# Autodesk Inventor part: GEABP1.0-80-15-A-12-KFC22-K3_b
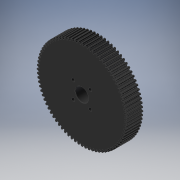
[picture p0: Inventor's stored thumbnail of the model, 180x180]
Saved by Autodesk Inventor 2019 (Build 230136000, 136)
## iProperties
Created: 2022-11
Part Number: GEABP1.0-80-15-A-12-KFC22-K3_b
Material: Generic
Catalog Web Link: www.cadenas.de
Description: GEABM, GEABMS, GEABMT, GEABP, GEABPS, GEABPT, GEABA, GEABAS, GEABAT_body-Plastic Spur Gears - Pressure Angle 20 Degrees, Module 0.5/0.8/1.0/1.5/2.0/2.5/3.0
Vendor: MISUMI
Document SubType Name: Modeling
Designer: psAdmin
Manufacturer: MISUMI
Mass: 72.9245 g
Surface Area: 182.111 cm^2
Volume: 72.9245 cm^3
Density: 1 g/cm^3
Appearance: PSOLRGB-175-175-175
Category: PARTsolutions
Company: MISUMI
Title: GEABP1.0-80-15-A-12-KFC22-K3
Author: Cadenas PARTsolutions
Comments: Plastic Spur Gears - Pressure Angle 20 Degrees, Module 0.5/0.8/1.0/1.5/2.0/2.5/3.0
PSOL_IDENT_0: {$CADENAS_DATA/23d-libs/misumi/metric/54_spur_gears/geabms20/geabms20.prj},408 {VTYP=3D},{NB=GEABP1.
PSOL_IDENT_1: 0-80-15-A-12-KFC22-K3_b},{LINA=GEABP1.0-80-15-A-12-KFC22-K3},{NN=GEABM, GEABMS, GEABMT, GEABP, GEABP
PSOL_IDENT_2: S, GEABPT, GEABA, GEABAS, GEABAT_body},{DATE=17.10.2022 23:48:33},{GEOMDATE=14.09.2022 05:11:00},{VE
PSOL_IDENT_3: RSION=},{LINEID=30},{WBVAR=MATSG,MATCR,NT,B,TS,PS,ALT1,ALT2,TPC,ALT11,ALT10,BS,ALT3,Z,J,ALT4,Q,R,S,T
PSOL_IDENT_4: ,ALT5,LFC,LTC,MALT5,ALT6,KFC,KTC,K},{WBNUMERIC=NT,B,BS,Z,J,Q,R,S,T,LFC,LTC,KFC,KTC,K}  {NB=GEABP1.0-
PSOL_IDENT_5: 80-15-A-12-KFC22-K3_b},{LINA=GEABP1.0-80-15-A-12-KFC22-K3},{KT=DUMMY},{PN=GEABP1.0-80-15-A-12-KFC22-
PSOL_IDENT_6: K3},{TYPE=GEABP},{MATSG=PW},{MATSGALG='MCN','MC Nylon','PW','Polyacetal White','PB','Polyacetal Blue'
PSOL_IDENT_7: },{MATCR=},{MATCRALG='','-','S45C','1045 Carbon Steel','SUS304','304 Stainless Steel'},{MOD=1.0},{MO
PSOL_IDENT_8: D1=1.0},{NT=80},{NTALG=15,16,18,20,22,24,25,26,28,30,32,35,36,40,45,48,50,55,60,70,75,80,90,100,120}
PSOL_IDENT_9: ,{B=15},{BALG=10,15},{TS=A},{TSALG='A','A','B','B'},{TSPN=-A},{PS=12},{PSALG='10','10','11','11','12'
PSOL_IDENT_10: ,'12','13','13','14','14','15','15','16','16','17','17','18','18','19','19','20','20','21','21','22'
PSOL_IDENT_11: ,'22','23','23','24','24','25','25','26','26','27','27','28','28'},{PSCRL='10','10','11','11','12','
PSOL_IDENT_12: 12','13','13','14','14','15','15','16','16','17','17','18','18','19','19','20','20','21','21','22','
PSOL_IDENT_13: 22','23','23','24','24','25','25','26','26','27','27','28','28'},{PSCRW='10','10','12','12','15','15'
PSOL_IDENT_14: ,'20','20'},{DD=80.0},{DD05=40},{DD08=64},{DD10=80},{DD15=120},{DD20=0},{DD25=0},{DD30=0},{D=82.0},{
PSOL_IDENT_15: D05=41},{D08=65.6},{D10=82},{D15=123},{D20=0},{D25=0},{D30=0},{G=77.50},{G05=38.75},{G08=62},{G10=77
PSOL_IDENT_16: .5},{G15=116.25},{G20=0},{G25=0},{G30=0},{H=0.0},{L=0},{LL1=0},{LL2=0.0},{M=-},{M3D=0},{P=12.00},{DD
PSOL_IDENT_17: 1=0},{CIFR=15},{CIFM=0},{CIFK=0},{CIFTAP=0},{ALT1=},{ALT1ALG='','Not applicable'},{ALT1PN=},{ALT2=},
PSOL_IDENT_18: {ALT2ALG='','Not applicable'},{TPC=N/A},{TPCALG='N/A'},{ALT2PN=},{KC=0},{ALT11=},{ALT11ALG='','Not a
PSOL_IDENT_19: pplicable'},{ALT11PN=},{DEG=0},{ALT10=},{ALT10ALG= '','Not applicable' },{ALT10PN=},{BS=0.0},{BSALG=
PSOL_IDENT_20: 0},{BSMIN=3},{BSMINALG=3.000},{BSMAX=0},{LL13D=0},{LL23D=0},{LBS=15},{ALT3=},{ALT3ALG= '','w/o Stepp
PSOL_IDENT_21: ed Hole','DHL','with DHL (Stepped Hole)','DHR','with DHR (Stepped Hole)' },{ALT3PN=},{ZJPN=},{ALT31=
PSOL_IDENT_22: 1},{ALT32=1},{Z=0},{ZALG=0},{ZMINL=14},{ZMAXL=73},{ZMINR=14},{ZMAXR=73},{ZPN=},{J=0.0},{JALG=0},{JMI
PSOL_IDENT_23: N=2},{JMAX=0},{JPN=},{ALT4=},{ALT4ALG= '','w/o WDH (Both Ends Stepped Hole)','WDH','with WDH (Both E
PSOL_IDENT_24: nds Stepped Hole)' },{ALT4PN=},{QRSTPN=},{LB=15.000},{Q=0},{QALG=0},{QMIN=14},{QMAX=73},{QPN=},{R=0}
PSOL_IDENT_25: ,{RALG=0},{RMIN=14},{RMAX=73},{RPN=},{S=0},{SALG=0},{SMIN=3},{SMAX=9},{SPN=},{T=0},{TALG=0},{TMIN=3}
PSOL_IDENT_26: ,{TMAX=0},{TPN=},{ALT5=},{ALT5ALG= '','w/o Side Slotted Hole','LFC','with LFC (Side Slotted Hole)','
PSOL_IDENT_27: LTC','with LTC (Side Slotted Hole)' },{LFC=0},{LFCALG=0},{LTC=0},{LTCALG=0},{LPCDMIN=20},{LPCDMAX=70
PSOL_IDENT_28: },{LCMAX=73},{MALT5=N/A},{MALT5ALG= 'N/A' },{LCMAX2=70},{C=0.0},{ALT5PN=},{ALT6=KFC},{ALT6ALG= '','w
PSOL_IDENT_29: /o Side Through Hole','KFC','with KFC (Side Through Hole)','KTC','with KTC (Side Through Hole)' },{A
PSOL_IDENT_30: LT6PN=-KFC},{KFTCPN=22-K3},{KFC=22},{KFCALG=[19:70/1]},{KFCPN=22},{KTC=0},{KTCALG=[0]},{KTCPN=},{KPC
PSOL_IDENT_31: DMIN1=19},{KPCDMAX1=-7},{KPCDMIN2=7},{KPCDMAX2=70},{K=3.0},{KALG=[3:6/0.5]},{KPCD=22},{KPN=-K3},{SCR
PSOL_IDENT_32: EW=0},{SCREWL=0},{AG=0},{PCD=22},{SHN=4},{SHDEG1=45},{SHDEG2=90},{PZQRDD2=12},{D1=1.125},{D2=2.25},{
PSOL_IDENT_33: D3=20},{D4=0.1},{D5=13.333333},{D6=12.307692},{D7=0.85},{D8=0.5},{D9=0.829978},{S1=15},{S2=0.5},{KR=
PSOL_IDENT_34: 15}
NB: GEABP1.0-80-15-A-12-KFC22-K3_b
NN: GEABM, GEABMS, GEABMT, GEABP, GEABPS, GEABPT, GEABA, GEABAS, GEABAT_body
NT: 80
NBSYN: $PN._b
LINA: GEABP1.0-80-15-A-12-KFC22-K3
CATALOG: Misumi
PN: GEABP1.0-80-15-A-12-KFC22-K3
MATSG: Polyacetal White
MATCR: -
MOD: 1.0
B: 15
TS: A
PS: 12
DD: 80
D: 82
G: 77.5
H: 0
L: 0
LL1: 0
LL2: 0
M: -
DD1: 0
ALT1: Not applicable
ALT2: Not applicable
TPC: N/A
ALT11: Not applicable
ALT10: Not applicable
BS: 0
ALT3: w/o Stepped Hole
Z: 0
J: 0
ALT4: w/o WDH (Both Ends Stepped Hole)
Q: 0
R: 0
S: 0
T: 0
ALT5: w/o Side Slotted Hole
LFC: 0
LTC: 0
MALT5: N/A
C: 0
ALT6: with KFC (Side Through Hole)
KFC: 22
KTC: 0
K: 3
SUPPLIER: MISUMI
ARTICLENO: GEABP1.0-80-15-A-12-KFC22-K3_b
BOMINFO: GEABP1.0-80-15-A-12-KFC22-K3
CREATOR: CADENAS GmbH
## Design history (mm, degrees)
sketch "_____3"
  geometry: L1 (15, 0)-(0, 0); L2 (0, 0)-(0, 40.5); L3 (0, 40.5)-(0.67, 43); L4 (0.67, 43)-(14.33, 43); L5 (14.33, 43)-(15, 40.5); L6 (15, 40.5)-(15, 0); L7 (15, 0)-(0, 0)
  constraints: 14 end point
revolve "Revolution1" sketch "_____3" stored, may be unused: angle "d0" = 360 deg
sketch "_____12"
  geometry: C1 r 164 at (0, 0); A1 r 41 centre (0, 0) between (-40.999, 0.33) and (-40.999, -0.33); A2 r 0.1 centre (-40.899, -0.329) between (-40.999, -0.33) and (-40.938, -0.421); A3 r 13.333 centre (-35.679, 11.831) between (-40.938, -0.421) and (-39.992, -0.785); A4 r 0.83 centre (-39.724, 0) between (-39.992, -0.785) and (-39.882, -0.815); A5 r 12.308 centre (-42.24, -12.894) between (-39.094, -0.996) and (-39.882, -0.815); A6 r 0.5 centre (-39.222, -1.479) between (-38.722, -1.46) and (-39.094, -0.996); A7 r 38.75 centre (0, 0) between (-38.722, -1.46) and (-38.718, -1.583); A8 r 0.5 centre (-39.217, -1.603) between (-39.052, -2.075) and (-38.718, -1.583); A9 r 12.308 centre (-43.122, 9.541) between (-39.823, -2.317) and (-39.052, -2.075); A10 r 0.83 centre (-39.601, -3.117) between (-39.823, -2.317) and (-39.931, -2.355); A11 r 13.333 centre (-34.641, -14.594) between (-39.931, -2.355) and (-40.845, -2.792); A12 r 0.1 centre (-40.798, -2.881) between (-40.845, -2.792) and (-40.898, -2.888); A13 r 41 centre (0, 0) between (-40.898, -2.888) and (-40.846, -3.546); A14 r 0.1 centre (-40.747, -3.537) between (-40.846, -3.546) and (-40.779, -3.632); A15 r 13.333 centre (-36.497, 8.995) between (-40.779, -3.632) and (-39.807, -3.921); A16 r 0.83 centre (-39.601, -3.117) between (-39.807, -3.921) and (-39.695, -3.941); A17 r 12.308 centre (-41.098, -16.169) between (-38.896, -4.06) and (-39.695, -3.941); A18 r 0.5 centre (-38.985, -4.552) between (-38.489, -4.494) and (-38.896, -4.06); A19 r 38.75 centre (0, 0) between (-38.489, -4.494) and (-38.474, -4.615); A20 r 0.5 centre (-38.971, -4.675) between (-38.769, -5.132) and (-38.474, -4.615); A21 r 12.308 centre (-43.737, 6.128) between (-39.518, -5.434) and (-38.769, -5.132); A22 r 0.83 centre (-39.235, -6.214) between (-39.518, -5.434) and (-39.623, -5.48); A23 r 13.333 centre (-33.389, -17.267) between (-39.623, -5.48) and (-40.5, -5.988); A24 r 0.1 centre (-40.447, -6.073) between (-40.5, -5.988) and (-40.546, -6.087); A25 r 41 centre (0, 0) between (-40.546, -6.087) and (-40.442, -6.74); A26 r 0.1 centre (-40.344, -6.723) between (-40.442, -6.74) and (-40.368, -6.82); A27 r 13.333 centre (-37.09, 6.104) between (-40.368, -6.82) and (-39.377, -7.032); A28 r 0.83 centre (-39.235, -6.214) between (-39.377, -7.032) and (-39.263, -7.044); A29 r 12.308 centre (-39.703, -19.343) between (-38.457, -7.099) and (-39.263, -7.044); A30 r 0.5 centre (-38.508, -7.596) between (-38.017, -7.5) and (-38.457, -7.099); A31 r 38.75 centre (0, 0) between (-38.017, -7.5) and (-37.993, -7.62); A32 r 0.5 centre (-38.484, -7.718) between (-38.247, -8.158) and (-37.993, -7.62); A33 r 12.308 centre (-44.083, 2.677) between (-38.97, -8.518) and (-38.247, -8.158); A34 r 0.83 centre (-38.626, -9.273) between (-38.97, -8.518) and (-39.071, -8.572); A35 r 13.333 centre (-31.931, -19.833) between (-39.071, -8.572) and (-39.905, -9.147); A36 r 0.1 centre (-39.846, -9.227) between (-39.905, -9.147) and (-39.943, -9.25); A37 r 41 centre (0, 0) between (-39.943, -9.25) and (-39.789, -9.892); A38 r 0.1 centre (-39.692, -9.868) between (-39.789, -9.892) and (-39.709, -9.966); A39 r 13.333 centre (-37.455, 3.175) between (-39.709, -9.966) and (-38.704, -10.1); A40 r 0.83 centre (-38.626, -9.273) between (-38.704, -10.1) and (-38.59, -10.103); A41 r 12.308 centre (-38.063, -22.399) between (-37.782, -10.094) and (-38.59, -10.103); A42 r 0.5 centre (-37.793, -10.594) between (-37.312, -10.459) and (-37.782, -10.094); A43 r 38.75 centre (0, 0) between (-37.312, -10.459) and (-37.278, -10.577); A44 r 0.5 centre (-37.759, -10.714) between (-37.489, -11.134) and (-37.278, -10.577); A45 r 12.308 centre (-44.157, -0.79) between (-38.182, -11.549) and (-37.489, -11.134); A46 r 0.83 centre (-37.78, -12.275) between (-38.182, -11.549) and (-38.278, -11.611); A47 r 13.333 centre (-30.277, -22.277) between (-38.278, -11.611) and (-39.065, -12.25); A48 r 0.1 centre (-38.999, -12.325) between (-39.065, -12.25) and (-39.094, -12.355); A49 r 41 centre (0, 0) between (-39.094, -12.355) and (-38.89, -12.983); A50 r 0.1 centre (-38.795, -12.952) between (-38.89, -12.983) and (-38.804, -13.051); A51 r 13.333 centre (-37.589, 0.227) between (-38.804, -13.051) and (-37.792, -13.105); A52 r 0.83 centre (-37.78, -12.275) between (-37.792, -13.105) and (-37.678, -13.099); A53 r 12.308 centre (-36.188, -25.316) between (-36.873, -13.028) and (-37.678, -13.099); A54 r 0.5 centre (-36.845, -13.527) between (-36.376, -13.355) and (-36.873, -13.028); A55 r 38.75 centre (0, 0) between (-36.376, -13.355) and (-36.334, -13.469); A56 r 0.5 centre (-36.802, -13.643) between (-36.499, -14.041) and (-36.334, -13.469); A57 r 12.308 centre (-43.959, -4.252) between (-37.158, -14.509) and (-36.499, -14.041); A58 r 0.83 centre (-36.7, -15.202) between (-37.158, -14.509) and (-37.249, -14.579); A59 r 13.333 centre (-28.435, -24.584) between (-37.249, -14.579) and (-37.983, -15.277); A60 r 0.1 centre (-37.911, -15.347) between (-37.983, -15.277) and (-38.004, -15.384); A61 r 41 centre (0, 0) between (-38.004, -15.384) and (-37.751, -15.995); A62 r 0.1 centre (-37.659, -15.956) between (-37.751, -15.995) and (-37.661, -16.056); A63 r 13.333 centre (-37.491, -2.723) between (-37.661, -16.056) and (-36.648, -16.03); A64 r 0.83 centre (-36.7, -15.202) between (-36.648, -16.03) and (-36.534, -16.015)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; 1 further point
  constraints: 1920 point on circle, 961 centre point
extrude "Extrusion1" cut sketch "_____12" distance "d1" = 15; taper "d2" = 0 deg
sketch "Sketch3"
  geometry: 1 further point
hole "Hole1" sketch "Sketch3" at (0, 0) diameter "d3" = 12; stored, may be unused: countersink angle "d7" = 90 deg, drill point angle "d9" = 0 deg; dims "d4" = 6, "d5" = 4, "d6" = 2, "d8" = 15
sketch "_____5"
  geometry: L1 (500, 0)-(-500, 0); L2 (14.7, 6)-(15, 6); L3 (15, 6)-(15, 6.3); L4 (15, 6.3)-(14.7, 6)
  constraints: 8 end point
revolve "Revolution2" sketch "_____5" stored, may be unused: angle "d10" = 360 deg
sketch "_____13"
  geometry: L1 (500, 0)-(-500, 0); L2 (0, 6.3)-(0, 6); L3 (0, 6)-(0.3, 6); L4 (0.3, 6)-(0, 6.3)
  constraints: 8 end point
revolve "Revolution3" sketch "_____13" stored, may be unused: angle "d11" = 360 deg
sketch "Sketch6"
  geometry: 1 further point
hole "Hole2" sketch "Sketch6" at (-7.144, 8.364) diameter "d12" = 3; stored, may be unused: countersink angle "d16" = 90 deg, drill point angle "d18" = 0 deg; dims "d13" = 6, "d14" = 4, "d15" = 2, "d17" = 15
pattern_linear "Rectangular Pattern1" dims "d21" = 15.55635, "d24" = 15.55635
body "Solid1"
